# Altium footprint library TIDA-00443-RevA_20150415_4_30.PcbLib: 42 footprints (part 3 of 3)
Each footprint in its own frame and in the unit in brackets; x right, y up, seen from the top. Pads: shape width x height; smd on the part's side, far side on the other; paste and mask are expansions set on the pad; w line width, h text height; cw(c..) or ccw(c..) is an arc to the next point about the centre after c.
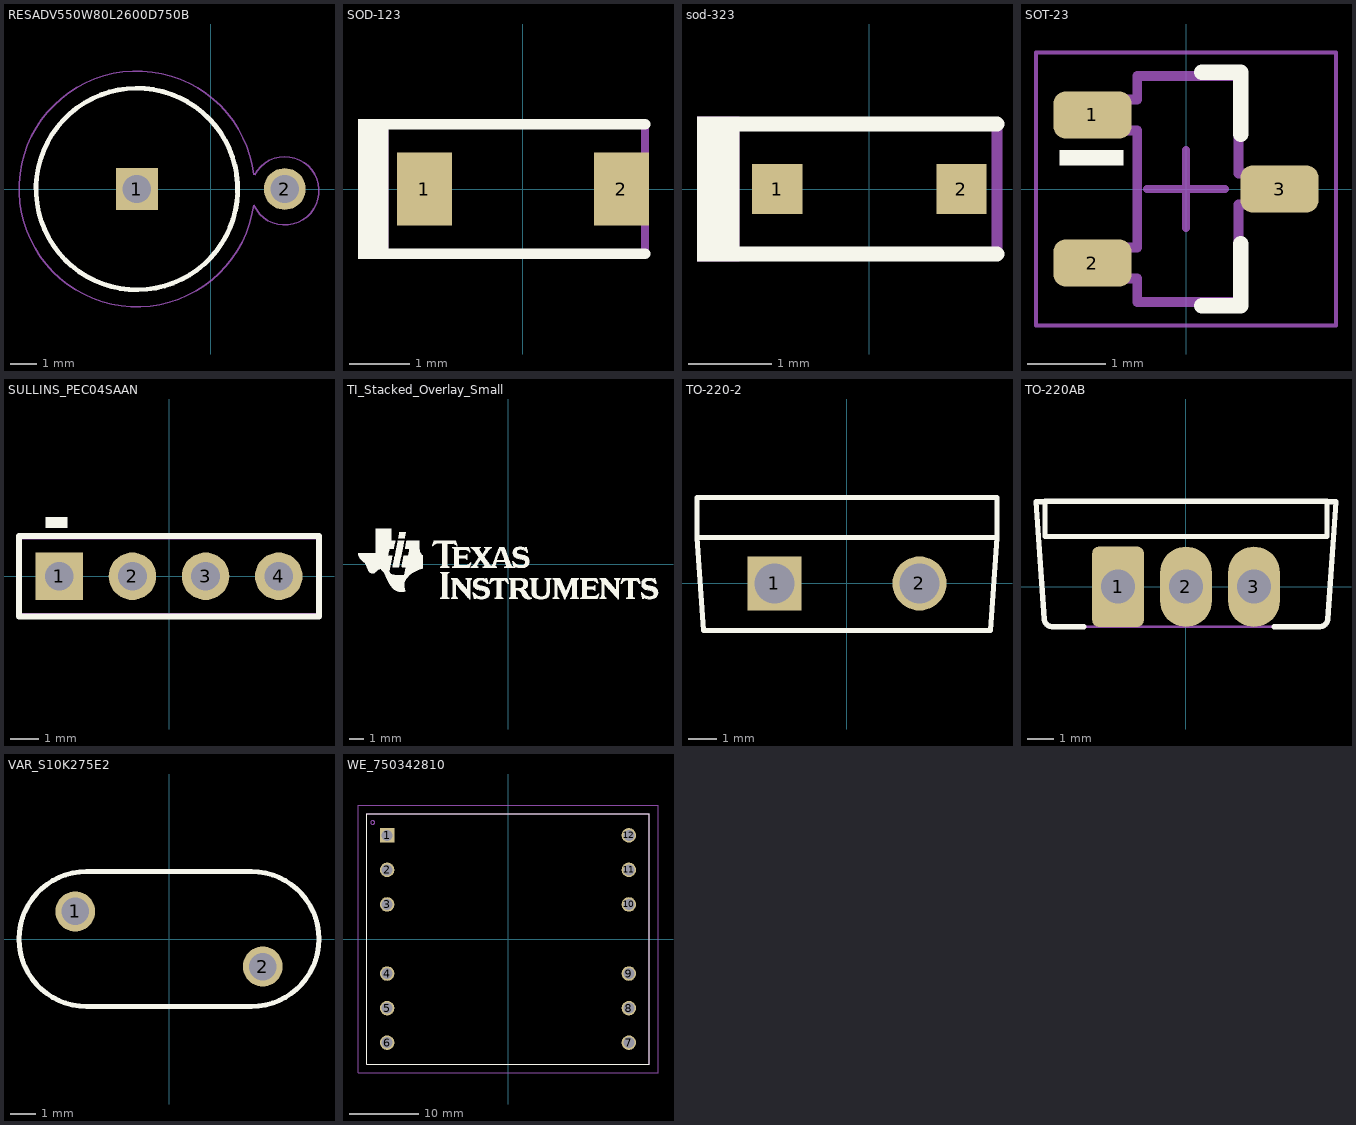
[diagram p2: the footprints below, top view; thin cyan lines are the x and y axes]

## RESADV550W80L2600D750B [mm] "RESISTOR, WIREWOUND, TH-2P, VERTICAL MOUNT"
height 29
pads (2):
  rect 1.554x1.554 / inner round 1.554 / far side rect 1.554x1.554 hole 1.054: 1(-2.75,0)
  round 1.554 hole 1.054: 2(2.75,0)
Top Overlay:
  lines w0.178: 0.96,0.544 cw(c-2.75,0) 0.96,0.546
Bottom Overlay:
  lines w0.178: -6.491,-0.258 ccw(c-2.75,0) -5.125,-2.902 ; -5.851,2.109 cw(c-2.75,0) -2.735,3.75 ; -2.658,-3.749 ccw(c-2.75,0) 0.152,-2.375 ; -0.439,2.953 cw(c-2.75,0) 0.96,0.544
Mechanical 5:
  lines w0.127: 0.96,0.544 cw(c-2.75,0) 0.96,0.546
  text ".Designator" at -2.946,1.016 h0.76
Mechanical 15:
  lines w0.05: 1.594,-0.599 cw(c-2.75,0) 1.603,0.531 ; 1.605,-0.609 ccw(c2.755,-0.07) 1.631,0.522
3D body: height 29, standoff 0, extent -6.47,-3.742 1,3.743

## SOD-123 [mm] "On Semi recommended land pattern"
height 1.35
pads (2):
  rect 0.915x1.22 smd: 1(-1.637,0) 2(1.637,0)
Top Overlay:
  rectangle: -2.743,-1.168 -2.235,1.168
  lines w0.178: -2.413,-1.079 2.032,-1.079 ; -2.413,1.079 2.032,1.079
Mechanical 5:
  rectangle: -2.743,-1.168 -2.235,1.168
  lines w0.127: -2.413,-1.079 2.032,-1.079 2.032,1.079 -2.413,1.079
  text ".Designator" at -0.457,0.61 h0.76
3D body: height 1.35, standoff 0, extent -1.932,-0.9 1.932,0.9

## sod-323 [mm] "NXP recommended land pattern"
height 1.15
pads (2):
  rect 0.6x0.6 smd paste-0.05: 1(-1.1,0) 2(1.1,0)
Top Overlay:
  rectangle: -2.057,-0.864 -1.549,0.864
  lines w0.178: -1.803,-0.775 0.1,-0.775 1.525,-0.775 ; -1.803,0.775 0.1,0.775 1.525,0.775
Mechanical 5:
  rectangle: -2.057,-0.864 -1.549,0.864
  lines w0.127: -1.803,-0.775 0.1,-0.775 1.525,-0.775 1.525,0.775 0.1,0.775 -1.803,0.775
  text ".Designator" at -0.813,-0.356 h0.76
3D body: height 1.1, standoff 0, extent -1.3,-0.675 1.3,0.675

## SOT-23 [mm] "SOT23, 3-Leads, Body 2.9x1.3mm, Pitch 0.95mm, Lead Span 2.5mm, IPC Medium Density"
height 1.1
pads (3):
  rrect50% 1x0.6 smd: 1(-1.2,0.95) 2(-1.2,-0.95) 3(1.2,0)
Top Overlay:
  rectangle: -1.625,0.3 -0.8,0.5
  lines w0.2: 0.2,-1.5 0.7,-1.5 0.7,-0.7 ; 0.2,1.5 0.7,1.5 0.7,0.7
Mechanical 5:
  lines w0.127: -1.16,-1.15 -0.625,-1.15 -0.625,-1.45 0.675,-1.45 0.675,-0.2 1.21,-0.2 1.21,0.2 0.675,0.2 0.675,1.45 -0.625,1.45 -0.625,1.15 -1.16,1.15 -1.16,0.75 -0.625,0.75 -0.625,-0.75 -1.16,-0.75 -1.16,-1.15
  text ".Designator" at -0.33,0.533 h0.76
Mechanical 15:
  lines w0.05: -1.925,-1.75 -1.925,1.75 1.925,1.75 1.925,-1.75 -1.925,-1.75
  lines w0.1: -0.5,0 0.5,0 ; 0,-0.5 0,0.5
3D body: height 1, standoff 0, extent -1.16,-1.45 1.21,1.45

## SULLINS_PEC04SAAN [mm] "SULLINS"
height 8.382
pads (4):
  rect 1.65x1.65 hole 1: 1(-3.81,0)
  round 1.65 hole 1: 2(-1.27,0) 3(1.27,0) 4(3.81,0)
Top Overlay:
  region: -3.53,1.676 -3.53,2.057 -4.292,2.057 -4.292,1.676
  lines w0.203: -5.207,-1.397 -5.207,1.397 5.207,1.397 5.207,-1.397 -5.207,-1.397
Mechanical 5:
  lines w0.102: -5.207,-1.333 -5.207,1.333 5.207,1.333 5.207,-1.333 -5.207,-1.333
  text ".Designator" at -0.864,-0.584 h0.76
3D body: height 2.54, standoff 0, extent -5.206,-1.333 5.206,1.333
3D body: height 8.38, standoff -3.05, extent 3.493,-0.317 4.128,0.318
3D body: height 8.38, standoff -3.05, extent 0.953,-0.317 1.588,0.318
3D body: height 8.38, standoff -3.05, extent -1.587,-0.317 -0.952,0.318
3D body: height 8.38, standoff -3.05, extent -4.127,-0.317 -3.492,0.318

## TI_Stacked_Overlay_Small [mm]
Top Overlay:
  drawing of 18 lines, arcs and shapes, not listed

## TO-220-2 [mm] "CREE"
height 20.066
pads (2):
  rect 1.9x1.9 hole 1.4: 1(-2.54,0)
  round 1.9 hole 1.4: 2(2.54,0)
Top Overlay:
  lines w0.178: -5.255,1.608 -5.255,3.008 5.255,3.008 5.255,1.608 ; -5.255,1.608 5.255,1.608 ; -5.255,1.608 -5.028,-1.642 5.028,-1.642 5.255,1.608
Mechanical 5:
  lines w0.127: -5.255,1.608 -5.028,-1.642 5.028,-1.642 5.255,1.608 ; -5.255,1.608 5.255,1.608 ; -5.255,1.608 -5.255,3.008 5.255,3.008 5.255,1.608
  text ".Designator" at 0.152,0.66 h0.76
3D body: height 19.47, standoff -3.96, extent -5.207,-1.575 5.207,3.124

## TO-220AB [mm] "Copied from Altium's version of TO3B"
height 19.4
pads (3):
  rrect25% 1.93x3 hole 1.27: 1(-2.54,0)
  oval 1.93x3 hole 1.27: 2(0,0) 3(2.54,0)
Top Overlay:
  lines w0.2: -5.27,3.175 -5.606,3.175 ; -5.27,3.185 -5.606,3.185 -5.606,3.175 ; -3.81,-1.495 -5,-1.495 cw(c-5,-1.195) -5.297,-1.237 cw(c-5,-1.195) -5.299,-1.216 -5.606,3.175 ; 3.302,-1.495 5,-1.495 ccw(c5,-1.195) 5.297,-1.237 ccw(c5,-1.195) 5.3,-1.216 5.607,3.175 ; 5.27,3.175 5.607,3.175 ; 5.27,3.185 5.607,3.185 5.607,3.175 ; -5.27,1.875 5.27,1.875 5.27,3.195 -5.27,3.195 -5.27,1.875
Mechanical 5:
  lines w0.1: -5.27,3.175 -5.606,3.175 ; -5.27,3.185 -5.606,3.185 -5.606,3.175 ; 5.27,3.175 5.607,3.175 ; 5.27,3.185 5.607,3.185 5.607,3.175 ; -5.606,3.175 -5.299,-1.216 ccw(c-5,-1.195) -5.297,-1.237 ccw(c-5,-1.195) -5,-1.495 5,-1.495 ccw(c5,-1.195) 5.297,-1.237 ccw(c5,-1.195) 5.3,-1.216 5.607,3.175 ; -5.27,1.875 -5.27,3.195 5.27,3.195 5.27,1.875 -5.27,1.875
  text ".Designator" at -0.483,0.61 h0.76
3D body: height 19.42, standoff -3.88, extent -5.606,-1.495 5.607,3.195

## VAR_S10K275E2 [mm] "EPCOS"
height 14.5
pads (2):
  round 1.6 hole 1.1: 1(-3.75,1.1) 2(3.75,-1.1)
Top Overlay:
  lines w0.2: -3.3,-2.7 cw(c-3.3,0) -3.3,2.7 3.3,2.7 cw(c3.3,0) 3.3,-2.7 -3.3,-2.7
Mechanical 5:
  lines w0.1: -3.3,-2.7 cw(c-3.3,0) -3.3,2.7 3.3,2.7 cw(c3.3,0) 3.3,-2.7 -3.3,-2.7
  text ".Designator" at 0.61,-0.203 h0.76
3D body: height 14.99, standoff 3.01, extent -5.976,-2.7 5.976,2.7
3D body: height 7, standoff -3, extent 3.328,-1.524 4.175,-0.676
3D body: height 7, standoff -3, extent -4.172,0.676 -3.325,1.524

## WE_750342810 [mm] "INDUCTOR, TH, 12-PIN"
height 39.63
pads (12):
  rect 2.1x2.1 / inner round 2.1 / far side rect 2.1x2.1 hole 1.6: 1(-17.5,15)
  round 2.1 hole 1.6: 2(-17.5,10) 3(-17.5,5) 4(-17.5,-5) 5(-17.5,-10) 6(-17.5,-15) 7(17.5,-15) 8(17.5,-10) 9(17.5,-5) 10(17.5,5) 11(17.5,10) 12(17.5,15)
Top Overlay:
  lines w0.178: -20.445,-18.1 20.445,-18.1 20.445,18.1 -20.445,18.1 -20.445,-18.1
Mechanical 5:
  circle w0.127: c-19.583,16.866 r0.279
  lines w0.127: -20.445,-18.1 20.445,-18.1 20.445,18.1 -20.445,18.1 -20.445,-18.1
  text ".Designator" at 0.737,1.194 h0.76
Mechanical 15:
  lines w0.05: -21.715,-19.37 -21.715,19.37 21.715,19.37 21.715,-19.37 -21.715,-19.37
Mechanical 17:
  text "LEAD LENGTH : 1.80 MM" at -10.033,7.747 h1
3D body: height 39.63, standoff 0, extent -20.445,-18.1 20.445,18.1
